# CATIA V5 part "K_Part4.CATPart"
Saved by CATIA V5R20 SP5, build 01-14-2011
Part number: 4 Siège
Bounding box of the stored display mesh (mm): x -34.99 to 34.994, y 0 to 186.26, z -103.311 to 34.99
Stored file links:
  G:\Khaled_CFAO_2011\SIL\SIL_GR1\gperrin\Khaled\CAD_CATIA\Khaled\K_Part4.CATPart
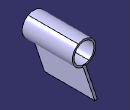
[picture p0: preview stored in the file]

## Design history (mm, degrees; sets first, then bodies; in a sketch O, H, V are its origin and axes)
Parameters
  LENGTH = 150 mm
Body1 (main body)
  Sketch1 on yz-plane, origin (0, 0, 0), H (0, 1, 0), V (0, 0, 1)
    axis line L1 (-56, 0) -> (79, 0)
    point P1 (-56, 0)
    point P3 (0, 35)
    line L2 (0, 35) -> (150, 35)
    line L3 (150, 35) -> (150, 30)
    line L4 (150, 30) -> (0, 30)
    line L5 (0, 30) -> (0, 35)
    length L3 = 5
    distance L4 L1 = 30
    length L2 = 150 {= LENGTH}
    coincidence: P1 H, P3 V
    horizontal: L1 H, L2 H, L4 H
    vertical: L3 V, L5 V
  Shaft1: profile Sketch1, axis Sketch1.L1, angle 360
  Sketch2 on yz-plane, origin (0, 0, 0), H (0, 1, 0), V (0, 0, 1)
    line L1 (0, -32) -> (36.2597, -103.3108)
    point P1 (0, -32)
    line L2 (150, -32) -> (186.2597, -103.3108)
    line L3 (0, -32) -> (150, -32)
    point P5 (0, -32)
    line L4 (36.2597, -103.3108) -> (186.2597, -103.3108)
    distance P1 O = 32
    length L2 = 80
    length L1 = 80
    length L4 = 150 {= LENGTH}
    length L3 = 150 {= LENGTH}
    coincidence: P1 V, P5 L1, P5 V
    parallelism: L2 L1
    horizontal: L3 H, L4 H
  Pad1: profile Sketch2, direction (1, 0, 0), length 4, mirrored extent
